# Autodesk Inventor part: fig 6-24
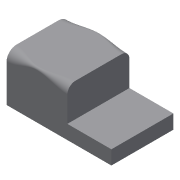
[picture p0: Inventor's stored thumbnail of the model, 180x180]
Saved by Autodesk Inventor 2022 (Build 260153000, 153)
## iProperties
Created: 2004-05
Part Number: fig 6-24
Document SubType Name: Modeling
Designer: CADCIM Technologies
Manufacturer: Standard
Standards Organization: Custom
Density: 1 g/cm^3
Material: Generic
Appearance: Default
Author: CADCIM Technologies
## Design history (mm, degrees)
node "Sketch1"
sketch "Sketch2"
  geometry: L1 (0.098, 47.711)-(0.098, 0.049); L2 (0.098, 0.049)-(-105.483, 0.049); L3 (-105.483, 0.049)-(-105.483, 14.192); L4 (-105.483, 14.192)-(-61.139, 14.192); L5 (-61.139, 14.192)-(-61.139, 47.711); L6 (-61.139, 47.711)-(0.098, 47.711)
  constraints: 12 end point, 3 parallel, 2 perpendicular, 1 vertical
extrude "Extrusion1" new body sketch "Sketch2" stored distance "d0" = 62.5; taper "d1" = 0 deg
fillet "Fillet9" dims "d61" = 10, "d62" = 8, "d63" = 2, "d64" = 5
fillet "Fillet10" dims "d65" = 8, "d66" = 10, "d67" = 2, "d68" = 5
body "Solid1"
